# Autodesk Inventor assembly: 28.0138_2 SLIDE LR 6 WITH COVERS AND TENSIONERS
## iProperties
Created: 2007-06
Part Number: 28.0138_2 SLIDE LR 6 WITH COVERS AND TENSIONERS
Document SubType Name: Assembly
Designer: Andy Moles
Author: Andy Moles
